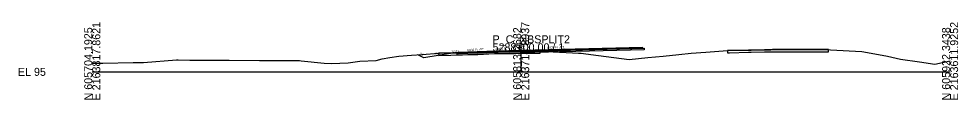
# Model space of a CAD drawing. Extents: x -26 to 1303, y -10 to 12038.
# Drawn here: x -25.7 to 302.8, y 4490.3 to 4517.3 of the extents above; entities that cross this region are included whole.
import ezdxf

# ---------------------------------------------------------------- set-up
doc = ezdxf.new("R2010")
doc.units = 0
for name, color, linetype in [('RD_GPK_XS_Cell', 7, 'Continuous'), ('RD_XS_Base', 7, 'Continuous'), ('RD_XS_ExGround', 7, 'Continuous'), ('RD_XS_ExPaveRet', 7, 'Continuous'), ('RD_XS_Greenside', 7, 'Continuous'), ('RD_XS_Pave', 7, 'Continuous'), ('RD_XS_PaveOvlay_CP', 7, 'Continuous'), ('RD_XS_TieSlope', 7, 'Continuous'), ('RD_XS_TX_Elev_EX', 7, 'Continuous'), ('RD_XS_TX_Elev_PR', 7, 'Continuous'), ('RD_XS_TX_ShdSlope', 7, 'Continuous'), ('RD_XS_TX_Slope', 7, 'Continuous')]:
    doc.layers.add(name, color=color, linetype=linetype)

msp = doc.modelspace()

# ---------------------------------------------------------------- linework, layer by layer
at = {"layer": 'RD_GPK_XS_Cell'}
for p, q in [((150, 4500), (150, 4510)), ((0, 4500), (150, 4500)), ((150, 4500), (300, 4500))]:
    msp.add_line(p, q, dxfattribs=at)
at = {"layer": 'RD_XS_Base'}
for p, q in [((150, 4507.14), (193.04, 4508.26)), ((193.04, 4507.76), (150, 4506.64)), ((174, 4507.76), (174, 4507.76)), ((174, 4507.76), (174, 4507.76)), ((192.54, 4508.24), (192.54, 4508.24)), ((193.04, 4508.26), (193.04, 4507.76)), ((193.04, 4508.22), (193.04, 4508.22)), ((128, 4506.43), (127.5, 4506.41)), ((127.5, 4506.41), (127.5, 4506.41)), ((127.5, 4506.41), (127.5, 4505.91)), ((127.5, 4505.91), (128, 4505.93)), ((138, 4506.83), (128, 4506.43)), ((128, 4506.43), (128, 4506.43)), ((128, 4505.93), (138, 4506.33)), ((128, 4505.93), (128, 4505.93)), ((150, 4507.14), (138, 4506.83)), ((138, 4506.83), (138, 4506.83)), ((138, 4506.33), (150, 4506.64)), ((138, 4506.33), (138, 4506.33)), ((150, 4506.64), (150, 4507.3)), ((150, 4507.3), (150, 4507.3)), ((150, 4507.3), (150, 4507.3)), ((150, 4507.3), (150, 4507.14)), ((150, 4507.14), (150, 4507.14)), ((150, 4506.64), (150, 4507.14)), ((150, 4507.14), (150, 4507.14)), ((150, 4507.14), (150, 4507.14)), ((150, 4506.64), (150, 4506.64)), ((174, 4507.26), (174, 4507.26)), ((174, 4507.26), (174, 4507.26))]:
    msp.add_line(p, q, dxfattribs=at)
at = {"layer": 'RD_XS_ExGround'}
msp.add_lwpolyline([(0, 4503.09), (2.44, 4503.04), (2.86, 4503.05), (3.66, 4503.07), (14.32, 4503.33), (17.95, 4503.33), (29.45, 4504.17), (29.99, 4504.21), (34.17, 4504.13), (35.85, 4504.06), (37.16, 4504.08), (41.3, 4504.14), (47.85, 4504.09), (58.52, 4503.96), (71.69, 4503.95), (72.49, 4503.95), (73.04, 4503.89), (81.16, 4503.02), (83.7, 4502.98), (89.48, 4503.14), (93.6, 4503.69), (99.31, 4504.01), (101.38, 4504.57), (104.06, 4505.05), (107.17, 4505.51), (111.62, 4505.85), (115.27, 4506.07), (121.18, 4506.49), (133.68, 4506.78), (134.82, 4506.83), (140.68, 4507.16), (142.15, 4507.18), (147.51, 4507.19), (156.6, 4507.24), (167.95, 4506.62), (169.99, 4506.49), (170.95, 4506.49), (171.83, 4506.42), (174.4, 4506.08), (187.74, 4504.36), (194.35, 4504.99), (199.62, 4505.5), (205.15, 4506.06), (209.41, 4506.5), (214.61, 4506.9), (222.15, 4507.45), (229.45, 4507.63), (230.47, 4507.65), (235.17, 4507.71), (237.27, 4507.76), (237.84, 4507.8), (239.29, 4507.78), (256.73, 4507.78), (257.5, 4507.78), (258.2, 4507.74), (269.09, 4507.09), (274.91, 4506.05), (278.07, 4505.51), (279.59, 4505.16), (282.61, 4504.44), (289.28, 4503.53), (294.62, 4502.68), (300, 4503.89)], dxfattribs=at)
at = {"layer": 'RD_XS_ExPaveRet'}
for points in [[(229.46, 4507.63), (229.45, 4507.63), (222.9, 4507.47), (222.15, 4507.45), (222.15, 4506.79), (222.15, 4506.7), (222.9, 4506.72), (229.45, 4506.88), (229.46, 4506.88), (230.06, 4506.89), (230.46, 4506.9), (230.47, 4506.9), (235.09, 4506.96), (235.17, 4506.96), (237.23, 4507.01), (237.27, 4507.01), (237.29, 4507.01), (237.84, 4507.05), (237.87, 4507.05), (239.29, 4507.03), (239.77, 4507.03), (256.73, 4507.03), (257.5, 4507.03), (257.5, 4507.03), (257.5, 4507.03), (257.5, 4507.03), (257.5, 4507.69), (257.5, 4507.78), (257.5, 4507.78), (257.5, 4507.78), (257.5, 4507.78), (256.73, 4507.78), (239.77, 4507.78), (239.29, 4507.78), (237.87, 4507.8), (237.84, 4507.8), (237.29, 4507.76), (237.27, 4507.76), (237.23, 4507.76), (235.17, 4507.71), (235.09, 4507.71), (230.47, 4507.65), (230.46, 4507.65), (230.06, 4507.64), (229.46, 4507.63)], [(229.46, 4507.63), (229.45, 4507.63), (222.9, 4507.47), (222.15, 4507.45), (222.15, 4506.79), (222.15, 4506.7), (222.9, 4506.72), (229.45, 4506.88), (229.46, 4506.88), (230.06, 4506.89), (230.46, 4506.9), (230.47, 4506.9), (235.09, 4506.96), (235.17, 4506.96), (237.23, 4507.01), (237.27, 4507.01), (237.29, 4507.01), (237.84, 4507.05), (237.87, 4507.05), (239.29, 4507.03), (239.77, 4507.03), (256.73, 4507.03), (257.5, 4507.03), (257.5, 4507.03), (257.5, 4507.69), (257.5, 4507.78), (257.5, 4507.78), (256.73, 4507.78), (239.77, 4507.78), (239.29, 4507.78), (237.87, 4507.8), (237.84, 4507.8), (237.29, 4507.76), (237.27, 4507.76), (237.23, 4507.76), (235.17, 4507.71), (235.09, 4507.71), (230.47, 4507.65), (230.46, 4507.65), (230.06, 4507.64), (229.46, 4507.63)], [(156.6, 4507.24), (147.51, 4507.19), (147.51, 4507.19), (142.15, 4507.18), (142.15, 4507.18), (140.68, 4507.16), (140.68, 4507.16), (140.68, 4507.16), (134.82, 4506.83), (134.82, 4506.83), (133.68, 4506.78), (121.18, 4506.49), (121.18, 4506.49), (121.18, 4506.49), (121.18, 4505.74), (121.18, 4505.74), (121.18, 4505.74), (121.18, 4505.74), (133.68, 4506.03), (134.82, 4506.08), (134.82, 4506.08), (140.68, 4506.41), (140.68, 4506.41), (140.68, 4506.41), (142.15, 4506.43), (142.15, 4506.43), (147.51, 4506.44), (147.51, 4506.44), (156.6, 4506.49), (156.6, 4506.49), (156.6, 4507.24), (156.6, 4507.24), (156.6, 4507.24)], [(156.6, 4507.24), (147.51, 4507.19), (142.15, 4507.18), (140.68, 4507.16), (134.82, 4506.83), (133.68, 4506.78), (121.18, 4506.49), (121.18, 4505.74), (133.68, 4506.03), (134.82, 4506.08), (140.68, 4506.41), (142.15, 4506.43), (147.51, 4506.44), (156.6, 4506.49), (156.6, 4506.49), (156.6, 4507.24), (156.6, 4507.24)]]:
    msp.add_lwpolyline(points, dxfattribs=at)
at = {"layer": 'RD_XS_Greenside'}
for p, q in [((116, 4504.92), (113.87, 4505.98)), ((126, 4506.58), (116, 4504.92))]:
    msp.add_line(p, q, dxfattribs=at)
at = {"layer": 'RD_XS_Pave'}
for p, q in [((192.54, 4508.56), (150, 4507.46)), ((192.54, 4508.4), (150, 4507.3)), ((150, 4507.3), (192.54, 4508.4)), ((150, 4507.14), (192.54, 4508.24)), ((174, 4508.08), (174, 4508.08)), ((174, 4508.08), (174, 4508.08)), ((174, 4507.92), (174, 4507.92)), ((174, 4507.92), (174, 4507.92)), ((174, 4507.92), (174, 4507.92)), ((174, 4507.92), (174, 4507.92)), ((174, 4507.76), (174, 4507.76)), ((174, 4507.76), (174, 4507.76)), ((192.54, 4508.4), (192.54, 4508.56)), ((192.54, 4508.56), (192.54, 4508.56)), ((192.54, 4508.24), (192.54, 4508.4)), ((192.54, 4508.4), (192.54, 4508.4)), ((138, 4507.14), (128, 4506.74)), ((128, 4506.59), (138, 4506.99)), ((138, 4506.99), (128, 4506.59)), ((128, 4506.43), (138, 4506.83)), ((128, 4506.74), (128, 4506.74)), ((128, 4506.74), (128, 4506.59)), ((128, 4506.59), (128, 4506.59)), ((128, 4506.59), (128, 4506.43)), ((150, 4507.46), (138, 4507.14)), ((138, 4506.99), (150, 4507.3)), ((150, 4507.3), (138, 4506.99)), ((138, 4507.14), (138, 4507.14)), ((138, 4506.83), (150, 4507.14)), ((138, 4506.99), (138, 4506.99)), ((138, 4506.99), (138, 4506.99)), ((138, 4506.83), (138, 4506.83)), ((150, 4507.46), (150, 4507.46)), ((150, 4507.3), (150, 4507.3)), ((150, 4507.3), (150, 4507.3)), ((150, 4507.3), (150, 4507.14)), ((150, 4507.3), (150, 4507.3)), ((150, 4507.14), (150, 4507.3)), ((150, 4507.3), (150, 4507.3)), ((150, 4507.3), (150, 4507.3)), ((150, 4507.14), (150, 4507.14)), ((150, 4507.14), (150, 4507.14))]:
    msp.add_line(p, q, dxfattribs=at)
at = {"layer": 'RD_XS_PaveOvlay_CP'}
for p, q in [((192.54, 4508.56), (150, 4507.46)), ((174, 4508.08), (174, 4508.08)), ((174, 4508.08), (174, 4508.08)), ((138, 4507.14), (128, 4506.74)), ((150, 4507.46), (138, 4507.14)), ((138, 4507.14), (138, 4507.14)), ((150, 4507.46), (150, 4507.46))]:
    msp.add_line(p, q, dxfattribs=at)
at = {"layer": 'RD_XS_TieSlope'}
msp.add_line((128, 4506.74), (126, 4506.58), dxfattribs=at)

# ---------------------------------------------------------------- texts
at = {"layer": 'RD_GPK_XS_Cell'}
for s, p in [('N 605704.1925', (0, 4490)), ('E 2163817.8621', (2.8, 4490)), ('N 605813.2682', (150, 4490)), ('E 2163714.8937', (152.8, 4490)), ('N 605922.3438', (300, 4490)), ('E 2163611.9252', (302.8, 4490))]:
    msp.add_text(s, height=2.8, rotation=90, dxfattribs=at).set_placement(p)
for s, p in [('P_C_NBSPLIT2', (140, 4510)), ('5288+00.00 / 1', (140, 4507.2)), ('EL 95', (-26, 4498.6))]:
    msp.add_text(s, height=2.8, dxfattribs=at).set_placement(p)
at = {"layer": 'RD_XS_TX_Elev_EX'}
msp.add_text('102.20', height=0.6, rotation=90, dxfattribs=at).set_placement((149.76, 4508.16))
at = {"layer": 'RD_XS_TX_Elev_PR'}
msp.add_text('102.46', height=1, rotation=90, dxfattribs=at).set_placement((151.25, 4507.82))
at = {"layer": 'RD_XS_TX_ShdSlope'}
msp.add_text('12.5:1', height=0.75, rotation=4.5739, dxfattribs=at).set_placement((125.59, 4506.77))
at = {"layer": 'RD_XS_TX_Slope'}
for s, rotation, p in [('0.040 FT./FT.', 2.2906, (130.99, 4507.26)), ('0.028 FT./FT.', 1.6039, (141, 4507.62)), ('0.028 FT./FT.', 1.6039, (159, 4508.12)), ('2:1', 333.4349, (114.36, 4506.19)), ('6:1', 9.4642, (119.89, 4505.98))]:
    msp.add_text(s, height=0.75, rotation=rotation, dxfattribs=at).set_placement(p)

doc.saveas('drawing.dxf')
